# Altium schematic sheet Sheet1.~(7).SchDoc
size A4
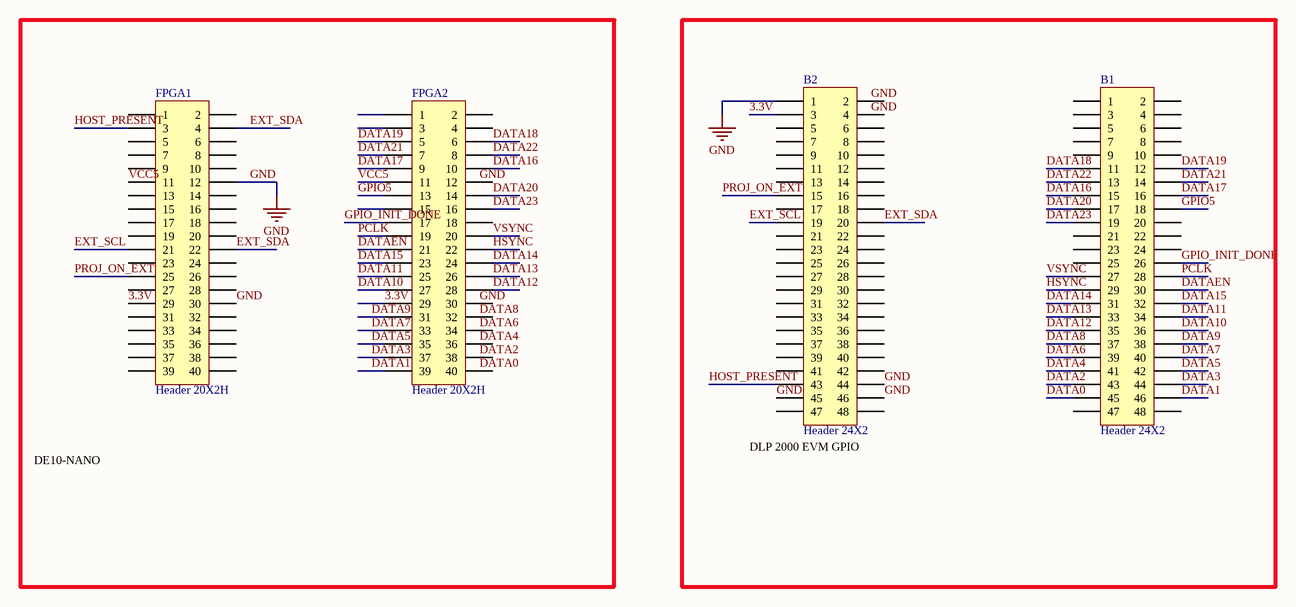
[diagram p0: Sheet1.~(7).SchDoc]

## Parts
B1  Header 24X2  [HDR2X24]
B2  Header 24X2  [HDR2X24]
FPGA1  Header 20X2H  [HDR2X20H]
FPGA2  Header 20X2H  [HDR2X20H]

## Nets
GND: B2.1 B2.44 B2.45 B2.46 FPGA1.12 FPGA1.30
3.3V: B2.3 FPGA1.29 FPGA2.29
DATA0: B1.45
DATA1: B1.46 FPGA2.39
DATA2: B1.43
DATA3: B1.44 FPGA2.37
DATA4: B1.41
DATA5: B1.42 FPGA2.35
DATA6: B1.39
DATA7: B1.40 FPGA2.33
DATA8: B1.37
DATA9: B1.38 FPGA2.31
DATA10: B1.36 FPGA2.27
DATA11: B1.34 FPGA2.25
DATA12: B1.35 FPGA2.28
DATA13: B1.33 FPGA2.26
DATA14: B1.31 FPGA2.24
DATA15: B1.32 FPGA2.23
DATA16: B1.15 FPGA2.10
DATA17: B1.16 FPGA2.9
DATA18: B1.11 FPGA2.6
DATA19: B1.12 FPGA2.5
DATA20: B1.17 FPGA2.14
DATA21: B1.14 FPGA2.7
DATA22: B1.13 FPGA2.8
DATA23: B1.19 FPGA2.16
DATAEN: B1.30 FPGA2.21
EXT_SCL: B2.19 FPGA1.21
EXT_SDA: B2.20 FPGA1.4 FPGA1.22
GPIO5: B1.18 FPGA2.13
GPIO_INIT_DONE: B1.26 FPGA2.17
HOST_PRESENT: B2.43 FPGA1.3
HSYNC: B1.29 FPGA2.22
PCLK: B1.28 FPGA2.19
PROJ_ON_EXT: B2.15 FPGA1.25
VCC5: FPGA1.11 FPGA2.11
VSYNC: B1.27 FPGA2.20

Not connected (* = marked no-connect by the designer): B1 1 2 3 4 5 6 7 8 9 10 20 21 22 23 24 25 47 48; B2 2 4 5 6 7 8 9 10 11 12 13 14 16 17 18 21 22 23 24 25 26 27 28 29 30 31 32 33 34 35 36 37 38 39 40 41 42 47 48; FPGA1 1 2 5 6 7 8 9 10 13 14 15 16 17 18 19 20 23 24 26 27 28 31 32 33 34 35 36 37 38 39 40; FPGA2 1 2 3 4 12 15 18 30 32 34 36 38 40

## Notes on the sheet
- DE10-NANO
- DLP 2000 EVM GPIO
- Labels drawn without touching a wire or pin: DATA0, DATA2, DATA4, DATA6, DATA8, GND

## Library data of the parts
B1 B2 = Header 24X2: Header, 24-Pin, Dual row
FPGA1 FPGA2 = Header 20X2H: Header, 20-Pin, Dual row, Right Angle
